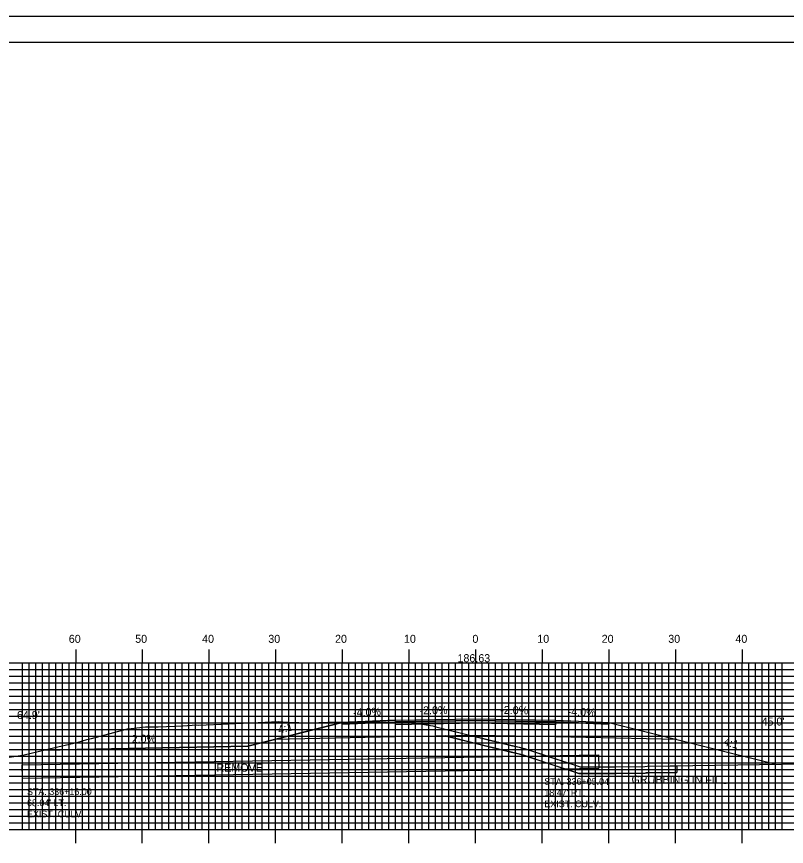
# Model space of a CAD drawing. Extents: x 1823573 to 1823916, y 442591 to 442811.
# Drawn here: x 1823669.4 to 1823784.9, y 442686.2 to 442810.5 of the extents above; entities that cross this region are included whole.
import ezdxf

# ---------------------------------------------------------------- set-up
doc = ezdxf.new("R2010")
doc.units = 0
for name, color, linetype in [('ANNOTATION', 7, 'Continuous'), ('BORDER', 7, 'Continuous'), ('D_Drainage_Culvert', 7, 'Continuous'), ('D_Roadway_Centerline', 7, 'Continuous'), ('D_Roadway_Centerline_Text', 7, 'Continuous'), ('D_Roadway_Edge_Shoulder', 7, 'Continuous'), ('D_Roadway_Edge_TW', 7, 'Continuous'), ('D_Roadway_Pavement', 7, 'Continuous'), ('D_Roadway_SlopeLines', 7, 'Continuous'), ('D_Roadway_SubGrade', 7, 'Continuous'), ('D_Text_Monospaced', 7, 'Continuous'), ('D_Text_Standard', 7, 'Continuous'), ('GRUBBING IN FILL', 7, 'Continuous'), ('H_V ANNOTATION', 7, 'Continuous'), ('MAJOR', 7, 'Continuous'), ('MINOR', 7, 'Continuous'), ('PLOT BOUNDARY', 7, 'Continuous'), ('S_Roadway_Centerline', 7, 'Continuous')]:
    doc.layers.add(name, color=color, linetype=linetype)

msp = doc.modelspace()

# ---------------------------------------------------------------- linework, layer by layer
at = {"layer": 'BORDER'}
msp.add_lwpolyline([(1823588.71, 442596.67), (1823908.71, 442596.67), (1823908.71, 442806.67), (1823588.71, 442806.67)], close=True, dxfattribs=at)
at = {"layer": 'D_Drainage_Culvert'}
for p, q in [((1823670.23, 442698.38), (1823756.75, 442699.89)), ((1823756.75, 442699.89), (1823756.78, 442697.89)), ((1823670.23, 442698.38), (1823670.27, 442696.38)), ((1823670.27, 442696.38), (1823756.78, 442697.89))]:
    msp.add_line(p, q, dxfattribs=at)
at = {"layer": 'D_Roadway_Centerline'}
msp.add_lwpolyline([(1823673.45, 442700.58), (1823704.13, 442701.19), (1823708.13, 442702.19), (1823718.31, 442704.74), (1823726.31, 442705.06), (1823738.31, 442705.3), (1823750.31, 442705.06), (1823758.31, 442704.74), (1823768.48, 442702.19), (1823772.48, 442701.19), (1823783.35, 442698.48)], dxfattribs=at)
at = {"layer": 'D_Roadway_Edge_Shoulder'}
for points in [[(1823726.31, 442705.06), (1823718.31, 442704.74), (1823718.31, 442704.49), (1823726.31, 442704.81)], [(1823750.31, 442705.06), (1823758.31, 442704.74), (1823758.31, 442704.49), (1823750.31, 442704.81)]]:
    msp.add_lwpolyline(points, close=True, dxfattribs=at)
at = {"layer": 'D_Roadway_Edge_TW'}
msp.add_lwpolyline([(1823726.31, 442704.81), (1823726.31, 442705.06), (1823738.31, 442705.3), (1823750.31, 442705.06), (1823750.31, 442704.81), (1823738.31, 442705.05)], close=True, dxfattribs=at)
at = {"layer": 'D_Roadway_Pavement'}
msp.add_lwpolyline([(1823726.31, 442704.39), (1823726.31, 442704.81), (1823738.31, 442705.05), (1823750.31, 442704.81), (1823750.31, 442704.39), (1823738.31, 442704.63)], close=True, dxfattribs=at)
at = {"layer": 'D_Roadway_SlopeLines'}
for points in [[(1823718.31, 442704.74), (1823704.13, 442701.19), (1823673.45, 442700.58)], [(1823758.31, 442704.74), (1823772.48, 442701.19), (1823783.35, 442698.48)]]:
    msp.add_lwpolyline(points, dxfattribs=at)
at = {"layer": 'D_Roadway_SubGrade'}
msp.add_lwpolyline([(1823726.31, 442702.56), (1823708.13, 442702.19), (1823718.31, 442704.74), (1823718.31, 442704.49), (1823726.31, 442704.81), (1823738.31, 442705.05), (1823750.31, 442704.81), (1823758.31, 442704.49), (1823758.31, 442704.74), (1823768.48, 442702.19), (1823750.31, 442702.56), (1823738.31, 442702.8)], close=True, dxfattribs=at)
at = {"layer": 'GRUBBING IN FILL'}
msp.add_line((1823768.48, 442698.25), (1823768.48, 442697.25), dxfattribs=at)
msp.add_line((1823768.48, 442698.25), (1823768.48, 442697.25), dxfattribs=at)
for points in [[(1823733.76, 442702.71), (1823737.62, 442702.78), (1823738.31, 442702.61), (1823738.31, 442701.58)], [(1823733.76, 442702.71), (1823737.62, 442702.78), (1823738.31, 442702.61), (1823738.31, 442701.58)], [(1823738.31, 442701.58), (1823738.31, 442702.61), (1823744.82, 442701.04), (1823745.3, 442700.9), (1823745.78, 442700.77), (1823749.67, 442699.5), (1823753.55, 442698.24), (1823754, 442698.06), (1823759.36, 442698.1), (1823763.68, 442698.14), (1823764.05, 442698.18), (1823768.48, 442698.25), (1823768.48, 442697.25), (1823763.92, 442697.16), (1823763.74, 442697.14), (1823759.37, 442697.1), (1823753.81, 442697.07), (1823749.35, 442698.55), (1823745.49, 442699.81), (1823744.1, 442700.17), (1823738.69, 442701.49)], [(1823738.31, 442701.58), (1823738.31, 442702.61), (1823744.82, 442701.04), (1823745.3, 442700.9), (1823745.78, 442700.77), (1823749.67, 442699.5), (1823753.55, 442698.24), (1823754, 442698.06), (1823759.36, 442698.1), (1823763.68, 442698.14), (1823764.05, 442698.18), (1823768.48, 442698.25), (1823768.48, 442697.25), (1823763.92, 442697.16), (1823763.74, 442697.14), (1823759.37, 442697.1), (1823753.81, 442697.07), (1823749.35, 442698.55), (1823745.49, 442699.81), (1823744.1, 442700.17), (1823738.69, 442701.49)]]:
    msp.add_lwpolyline(points, close=True, dxfattribs=at)
msp.add_lwpolyline([(1823733.76, 442702.71), (1823743.62, 442700.27), (1823744.58, 442700.06), (1823745.49, 442699.81), (1823753.22, 442697.29), (1823753.81, 442697.07), (1823754.24, 442697.06), (1823759.37, 442697.1), (1823763.74, 442697.14), (1823764.11, 442697.18), (1823768.48, 442697.25)], dxfattribs=at)
msp.add_lwpolyline([(1823733.76, 442702.71), (1823743.62, 442700.27), (1823744.58, 442700.06), (1823745.49, 442699.81), (1823753.22, 442697.29), (1823753.81, 442697.07), (1823754.24, 442697.06), (1823759.37, 442697.1), (1823763.74, 442697.14), (1823764.11, 442697.18), (1823768.48, 442697.25)], dxfattribs=at)
at = {"layer": 'MAJOR'}
for p, q in [((1823678.31, 442715.67), (1823678.31, 442713.67)), ((1823688.31, 442715.67), (1823688.31, 442713.67)), ((1823698.31, 442715.67), (1823698.31, 442713.67)), ((1823708.31, 442715.67), (1823708.31, 442713.67)), ((1823718.31, 442715.67), (1823718.31, 442713.67)), ((1823728.31, 442715.67), (1823728.31, 442713.67)), ((1823738.31, 442715.67), (1823738.31, 442713.67)), ((1823748.31, 442715.67), (1823748.31, 442713.67)), ((1823758.31, 442715.67), (1823758.31, 442713.67)), ((1823768.31, 442715.67), (1823768.31, 442713.67)), ((1823778.31, 442715.67), (1823778.31, 442713.67)), ((1823598.31, 442713.67), (1823878.31, 442713.67)), ((1823598.31, 442713.67), (1823878.31, 442713.67)), ((1823678.31, 442688.67), (1823678.31, 442713.67)), ((1823688.31, 442688.67), (1823688.31, 442713.67)), ((1823698.31, 442688.67), (1823698.31, 442713.67)), ((1823708.31, 442688.67), (1823708.31, 442713.67)), ((1823718.31, 442688.67), (1823718.31, 442713.67)), ((1823728.31, 442688.67), (1823728.31, 442713.67)), ((1823738.31, 442688.67), (1823738.31, 442713.67)), ((1823748.31, 442688.67), (1823748.31, 442713.67)), ((1823758.31, 442688.67), (1823758.31, 442713.67)), ((1823768.31, 442688.67), (1823768.31, 442713.67)), ((1823778.31, 442688.67), (1823778.31, 442713.67)), ((1823598.31, 442708.67), (1823878.31, 442708.67)), ((1823598.31, 442703.67), (1823878.31, 442703.67)), ((1823598.31, 442698.67), (1823878.31, 442698.67)), ((1823598.31, 442693.67), (1823878.31, 442693.67)), ((1823598.31, 442688.67), (1823878.31, 442688.67)), ((1823598.31, 442688.67), (1823878.31, 442688.67)), ((1823678.31, 442686.66), (1823678.31, 442688.67)), ((1823688.31, 442686.66), (1823688.31, 442688.67)), ((1823698.31, 442686.66), (1823698.31, 442688.67)), ((1823708.31, 442686.66), (1823708.31, 442688.67)), ((1823718.31, 442686.66), (1823718.31, 442688.67)), ((1823728.31, 442686.66), (1823728.31, 442688.67)), ((1823738.31, 442686.66), (1823738.31, 442688.67)), ((1823748.31, 442686.66), (1823748.31, 442688.67)), ((1823758.31, 442686.66), (1823758.31, 442688.67)), ((1823768.31, 442686.66), (1823768.31, 442688.67)), ((1823778.31, 442686.66), (1823778.31, 442688.67))]:
    msp.add_line(p, q, dxfattribs=at)
at = {"layer": 'MINOR'}
for p, q in [((1823670.31, 442688.67), (1823670.31, 442713.67)), ((1823671.31, 442688.67), (1823671.31, 442713.67)), ((1823672.31, 442688.67), (1823672.31, 442713.67)), ((1823673.31, 442688.67), (1823673.31, 442713.67)), ((1823674.31, 442688.67), (1823674.31, 442713.67)), ((1823675.31, 442688.67), (1823675.31, 442713.67)), ((1823676.31, 442688.67), (1823676.31, 442713.67)), ((1823677.31, 442688.67), (1823677.31, 442713.67)), ((1823679.31, 442688.67), (1823679.31, 442713.67)), ((1823680.31, 442688.67), (1823680.31, 442713.67)), ((1823681.31, 442688.67), (1823681.31, 442713.67)), ((1823682.31, 442688.67), (1823682.31, 442713.67)), ((1823683.31, 442688.67), (1823683.31, 442713.67)), ((1823684.31, 442688.67), (1823684.31, 442713.67)), ((1823685.31, 442688.67), (1823685.31, 442713.67)), ((1823686.31, 442688.67), (1823686.31, 442713.67)), ((1823687.31, 442688.67), (1823687.31, 442713.67)), ((1823689.31, 442688.67), (1823689.31, 442713.67)), ((1823690.31, 442688.67), (1823690.31, 442713.67)), ((1823691.31, 442688.67), (1823691.31, 442713.67)), ((1823692.31, 442688.67), (1823692.31, 442713.67)), ((1823693.31, 442688.67), (1823693.31, 442713.67)), ((1823694.31, 442688.67), (1823694.31, 442713.67)), ((1823695.31, 442688.67), (1823695.31, 442713.67)), ((1823696.31, 442688.67), (1823696.31, 442713.67)), ((1823697.31, 442688.67), (1823697.31, 442713.67)), ((1823699.31, 442688.67), (1823699.31, 442713.67)), ((1823700.31, 442688.67), (1823700.31, 442713.67)), ((1823701.31, 442688.67), (1823701.31, 442713.67)), ((1823702.31, 442688.67), (1823702.31, 442713.67)), ((1823703.31, 442688.67), (1823703.31, 442713.67)), ((1823704.31, 442688.67), (1823704.31, 442713.67)), ((1823705.31, 442688.67), (1823705.31, 442713.67)), ((1823706.31, 442688.67), (1823706.31, 442713.67)), ((1823707.31, 442688.67), (1823707.31, 442713.67)), ((1823709.31, 442688.67), (1823709.31, 442713.67)), ((1823710.31, 442688.67), (1823710.31, 442713.67)), ((1823711.31, 442688.67), (1823711.31, 442713.67)), ((1823712.31, 442688.67), (1823712.31, 442713.67)), ((1823713.31, 442688.67), (1823713.31, 442713.67)), ((1823714.31, 442688.67), (1823714.31, 442713.67)), ((1823715.31, 442688.67), (1823715.31, 442713.67)), ((1823716.31, 442688.67), (1823716.31, 442713.67)), ((1823717.31, 442688.67), (1823717.31, 442713.67)), ((1823719.31, 442688.67), (1823719.31, 442713.67)), ((1823720.31, 442688.67), (1823720.31, 442713.67)), ((1823721.31, 442688.67), (1823721.31, 442713.67)), ((1823722.31, 442688.67), (1823722.31, 442713.67)), ((1823723.31, 442688.67), (1823723.31, 442713.67)), ((1823724.31, 442688.67), (1823724.31, 442713.67)), ((1823725.31, 442688.67), (1823725.31, 442713.67)), ((1823726.31, 442688.67), (1823726.31, 442713.67)), ((1823727.31, 442688.67), (1823727.31, 442713.67)), ((1823729.31, 442688.67), (1823729.31, 442713.67)), ((1823730.31, 442688.67), (1823730.31, 442713.67)), ((1823731.31, 442688.67), (1823731.31, 442713.67)), ((1823732.31, 442688.67), (1823732.31, 442713.67)), ((1823733.31, 442688.67), (1823733.31, 442713.67)), ((1823734.31, 442688.67), (1823734.31, 442713.67)), ((1823735.31, 442688.67), (1823735.31, 442713.67)), ((1823736.31, 442688.67), (1823736.31, 442713.67)), ((1823737.31, 442688.67), (1823737.31, 442713.67)), ((1823739.31, 442688.67), (1823739.31, 442713.67)), ((1823740.31, 442688.67), (1823740.31, 442713.67)), ((1823741.31, 442688.67), (1823741.31, 442713.67)), ((1823742.31, 442688.67), (1823742.31, 442713.67)), ((1823743.31, 442688.67), (1823743.31, 442713.67)), ((1823744.31, 442688.67), (1823744.31, 442713.67)), ((1823745.31, 442688.67), (1823745.31, 442713.67)), ((1823746.31, 442688.67), (1823746.31, 442713.67)), ((1823747.31, 442688.67), (1823747.31, 442713.67)), ((1823749.31, 442688.67), (1823749.31, 442713.67)), ((1823750.31, 442688.67), (1823750.31, 442713.67)), ((1823751.31, 442688.67), (1823751.31, 442713.67)), ((1823752.31, 442688.67), (1823752.31, 442713.67)), ((1823753.31, 442688.67), (1823753.31, 442713.67)), ((1823754.31, 442688.67), (1823754.31, 442713.67)), ((1823755.31, 442688.67), (1823755.31, 442713.67)), ((1823756.31, 442688.67), (1823756.31, 442713.67)), ((1823757.31, 442688.67), (1823757.31, 442713.67)), ((1823759.31, 442688.67), (1823759.31, 442713.67)), ((1823760.31, 442688.67), (1823760.31, 442713.67)), ((1823761.31, 442688.67), (1823761.31, 442713.67)), ((1823762.31, 442688.67), (1823762.31, 442713.67)), ((1823763.31, 442688.67), (1823763.31, 442713.67)), ((1823764.31, 442688.67), (1823764.31, 442713.67)), ((1823765.31, 442688.67), (1823765.31, 442713.67)), ((1823766.31, 442688.67), (1823766.31, 442713.67)), ((1823767.31, 442688.67), (1823767.31, 442713.67)), ((1823769.31, 442688.67), (1823769.31, 442713.67)), ((1823770.31, 442688.67), (1823770.31, 442713.67)), ((1823771.31, 442688.67), (1823771.31, 442713.67)), ((1823772.31, 442688.67), (1823772.31, 442713.67)), ((1823773.31, 442688.67), (1823773.31, 442713.67)), ((1823774.31, 442688.67), (1823774.31, 442713.67)), ((1823775.31, 442688.67), (1823775.31, 442713.67)), ((1823776.31, 442688.67), (1823776.31, 442713.67)), ((1823777.31, 442688.67), (1823777.31, 442713.67)), ((1823779.31, 442688.67), (1823779.31, 442713.67)), ((1823780.31, 442688.67), (1823780.31, 442713.67)), ((1823781.31, 442688.67), (1823781.31, 442713.67)), ((1823782.31, 442688.67), (1823782.31, 442713.67)), ((1823783.31, 442688.67), (1823783.31, 442713.67)), ((1823784.31, 442688.67), (1823784.31, 442713.67)), ((1823598.31, 442712.67), (1823878.31, 442712.67)), ((1823598.31, 442711.67), (1823878.31, 442711.67)), ((1823598.31, 442710.67), (1823878.31, 442710.67)), ((1823598.31, 442709.67), (1823878.31, 442709.67)), ((1823598.31, 442707.67), (1823878.31, 442707.67)), ((1823598.31, 442706.67), (1823878.31, 442706.67)), ((1823598.31, 442705.67), (1823878.31, 442705.67)), ((1823598.31, 442704.67), (1823878.31, 442704.67)), ((1823598.31, 442702.67), (1823878.31, 442702.67)), ((1823598.31, 442701.67), (1823878.31, 442701.67)), ((1823598.31, 442700.67), (1823878.31, 442700.67)), ((1823598.31, 442699.67), (1823878.31, 442699.67)), ((1823598.31, 442697.67), (1823878.31, 442697.67)), ((1823598.31, 442696.67), (1823878.31, 442696.67)), ((1823598.31, 442695.67), (1823878.31, 442695.67)), ((1823598.31, 442694.67), (1823878.31, 442694.67)), ((1823598.31, 442692.67), (1823878.31, 442692.67)), ((1823598.31, 442691.67), (1823878.31, 442691.67)), ((1823598.31, 442690.67), (1823878.31, 442690.67)), ((1823598.31, 442689.67), (1823878.31, 442689.67))]:
    msp.add_line(p, q, dxfattribs=at)
at = {"layer": 'PLOT BOUNDARY'}
msp.add_lwpolyline([(1823572.52, 442590.55), (1823912.52, 442590.55), (1823912.52, 442810.55), (1823572.52, 442810.55)], close=True, dxfattribs=at)
at = {"layer": 'S_Roadway_Centerline'}
msp.add_lwpolyline([(1823661.47, 442698.52), (1823670.38, 442699.84), (1823674.33, 442700.79), (1823678.69, 442701.79), (1823680.01, 442702.2), (1823680.67, 442702.35), (1823686.09, 442703.79), (1823686.65, 442703.84), (1823688.81, 442704.07), (1823690.69, 442704.06), (1823694.37, 442704.23), (1823696.51, 442704.38), (1823696.78, 442704.35), (1823705.67, 442704.74), (1823708.68, 442704.86), (1823710.15, 442704.8), (1823713.46, 442704.69), (1823716.15, 442704.76), (1823722.2, 442704.9), (1823723.65, 442704.82), (1823728.76, 442704.64), (1823729.38, 442704.66), (1823730.91, 442704.39), (1823731.88, 442704.24), (1823732.35, 442704.09), (1823743.84, 442701.25), (1823744.82, 442701.04), (1823745.78, 442700.77), (1823753.55, 442698.24), (1823754, 442698.06), (1823754.25, 442698.06), (1823759.36, 442698.1), (1823763.68, 442698.14), (1823764.05, 442698.18), (1823774.36, 442698.35), (1823794.06, 442698.63)], dxfattribs=at)

# ---------------------------------------------------------------- texts
at = {"layer": 'ANNOTATION'}
for s, rotation, p in [('-2.0%', 1.1458, (1823729.91, 442705.93)), ('-2.0%', 358.8542, (1823741.99, 442706.02)), ('-4.0%', 2.2906, (1823719.94, 442705.61)), ('-4.0%', 357.7094, (1823752.1, 442705.79)), ('4:1', 14.0362, (1823708.82, 442703.04)), ('2.0%', 1.1458, (1823686.72, 442701.65)), ('4:1', 345.9638, (1823775.42, 442701.32))]:
    msp.add_text(s, height=1.2, rotation=rotation, dxfattribs=at).set_placement(p)
at = {"layer": 'D_Roadway_Centerline'}
for s, p in [('C', (1823738.3, 442705.3)), ('L', (1823738.31, 442705.29))]:
    msp.add_text(s, height=0.0146, dxfattribs=at).set_placement(p)
at = {"layer": 'D_Roadway_Centerline_Text'}
msp.add_text('186.63', height=1.2, dxfattribs=at).set_placement((1823735.59, 442713.77))
at = {"layer": 'D_Text_Monospaced'}
for s, p in [('STA. 336+05.04', (1823748.62, 442695.38)), ('STA. 336+16.00', (1823671.01, 442693.86)), ("18.47' RT.", (1823748.62, 442693.71)), ("68.04' LT.", (1823671.01, 442692.19)), ('EXIST. CULV.', (1823748.62, 442692.03)), ('EXIST. CULV.', (1823671.01, 442690.51))]:
    msp.add_text(s, height=1, dxfattribs=at).set_placement(p)
at = {"layer": 'D_Text_Standard'}
for s, p in [("64.9'", (1823669.5, 442705.25)), ("45.0'", (1823781.21, 442704.27)), ('REMOVE', (1823699.43, 442697.35))]:
    msp.add_text(s, height=1.2, dxfattribs=at).set_placement(p)
at = {"layer": 'GRUBBING IN FILL'}
msp.add_text('GRUBBING IN FILL', height=1.2, rotation=359.8053, dxfattribs=at).set_placement((1823761.7, 442695.58))
at = {"layer": 'H_V ANNOTATION'}
for s, p in [('60', (1823677.28, 442716.67)), ('50', (1823687.24, 442716.67)), ('40', (1823697.28, 442716.67)), ('30', (1823707.21, 442716.67)), ('20', (1823717.22, 442716.67)), ('10', (1823727.56, 442716.67)), ('0', (1823737.83, 442716.67)), ('10', (1823747.56, 442716.67)), ('20', (1823757.22, 442716.67)), ('30', (1823767.21, 442716.67)), ('40', (1823777.28, 442716.67))]:
    msp.add_text(s, height=1.2, dxfattribs=at).set_placement(p)
at = {"layer": 'S_Roadway_Centerline'}
for s, p in [('C', (1823708.68, 442704.86)), ('L', (1823708.68, 442704.85))]:
    msp.add_text(s, height=0.0146, dxfattribs=at).set_placement(p)

doc.saveas('drawing.dxf')
